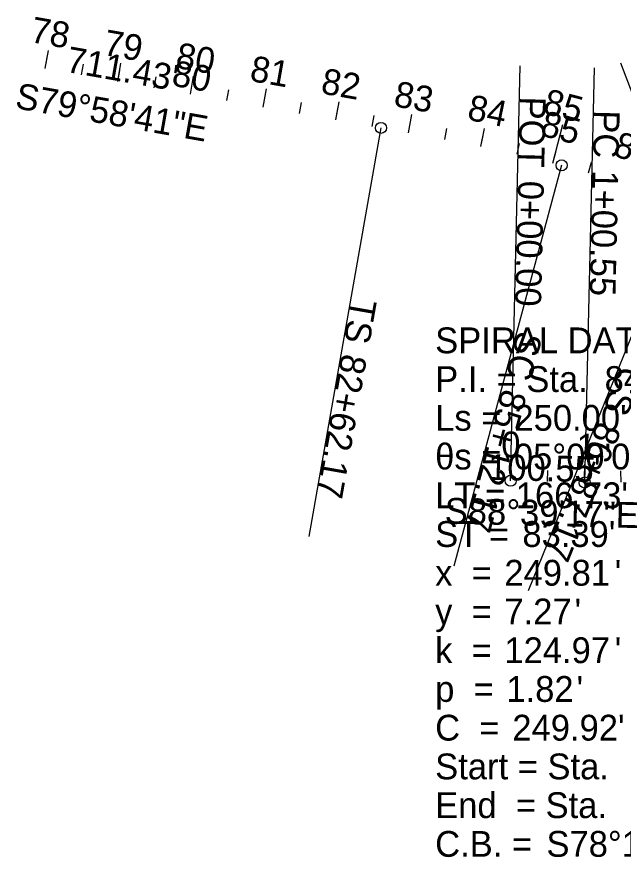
# Model space of a CAD drawing. Extents: x 2000474 to 2003418, y 251807 to 253801.
# Drawn here: x 2000474 to 2001296, y 252341 to 253480 of the extents above; entities that cross this region are included whole.
import ezdxf

# ---------------------------------------------------------------- set-up
doc = ezdxf.new("R2010")
doc.units = 0
for name, color, linetype in [('BD_X_Building', 7, 'Continuous'), ('DR_X_Flow_Arrow', 7, 'Continuous'), ('DV_X_Lot_Line', 7, 'Continuous'), ('DV_X_Property_Line', 7, 'Continuous'), ('DV_X_Township_Line', 7, 'Continuous'), ('GE_P_Alignment_100_Stations', 7, 'Continuous'), ('RW_P_Text', 7, 'Continuous'), ('RW_X_CL_100_Stations', 7, 'Continuous'), ('RW_X_CL_500_Stations', 7, 'Continuous'), ('SC_Scratch3', 7, 'Continuous'), ('SC_Scratch5', 7, 'Continuous'), ('SC_Shading1', 7, 'Continuous'), ('TX_X_50', 7, 'Continuous')]:
    doc.layers.add(name, color=color, linetype=linetype)

msp = doc.modelspace()

# ---------------------------------------------------------------- linework, layer by layer
at = {"layer": 'DR_X_Flow_Arrow'}
for p, q in [((2001143.5, 252851.1), (2001156.7, 253413.4)), ((2001490.7, 252890.5), (2001293.1, 253417.1)), ((2001244, 252848.7), (2001257.2, 253411)), ((2001143.5, 252851.1), (2001144.1, 252876.1)), ((2001243.5, 252848.7), (2001244.1, 252873.7)), ((2001193.5, 252849.9), (2001193.9, 252864.9)), ((2001293.5, 252849.4), (2001292.7, 252864.4))]:
    msp.add_line(p, q, dxfattribs=at)
for centre in [(2001143.5, 252851.1), (2001244, 252848.7)]:
    msp.add_circle(centre, 7.5, dxfattribs=at)
at = {"layer": 'DV_X_Lot_Line'}
for p, q in [((2001143.5, 252851.1), (2001144.1, 252876.1)), ((2001243.5, 252848.7), (2001243.8, 252863.7))]:
    msp.add_line(p, q, dxfattribs=at)
at = {"layer": 'DV_X_Property_Line'}
for p, q in [((2000512.7, 253409.8), (2000515.3, 253424.6)), ((2000611.2, 253392.4), (2000613.8, 253407.2)), ((2000709.7, 253375), (2000714, 253399.6)), ((2000808.1, 253357.6), (2000810.7, 253372.4)), ((2000906.6, 253340.2), (2000909.2, 253355)), ((2001005.1, 253322.8), (2001007.7, 253337.5)), ((2001200.8, 253281.8), (2001214.3, 253333.8)), ((2001103.3, 253304.2), (2001106.3, 253318.9))]:
    msp.add_line(p, q, dxfattribs=at)
at = {"layer": 'RW_P_Text'}
for p, q in [((2001143.5, 252851.1), (2001156.7, 253413.4)), ((2001490.7, 252890.5), (2001293.1, 253417.1)), ((2001244, 252848.7), (2001257.2, 253411)), ((2001143.5, 252851.1), (2001144.1, 252876.1))]:
    msp.add_line(p, q, dxfattribs=at)
for centre in [(2001143.5, 252851.1), (2001244, 252848.7)]:
    msp.add_circle(centre, 7.5, dxfattribs=at)
at = {"layer": 'RW_X_CL_100_Stations'}
for p, q in [((2001143.5, 252851.1), (2001156.7, 253413.4)), ((2001490.7, 252890.5), (2001293.1, 253417.1)), ((2001244, 252848.7), (2001257.2, 253411)), ((2000967.8, 253329.4), (2000869.9, 252775.4)), ((2001212.6, 253278.7), (2001066.8, 252735.5)), ((2001378.4, 253223.2), (2001167.5, 252701.7))]:
    msp.add_line(p, q, dxfattribs=at)
for centre in [(2000967.8, 253329.4), (2001212.6, 253278.7), (2001143.5, 252851.1), (2001244, 252848.7)]:
    msp.add_circle(centre, 7.5, dxfattribs=at)
at = {"layer": 'SC_Scratch3'}
for p, q in [((2000709.7, 253375), (2000714, 253399.6)), ((2000967.8, 253329.4), (2000869.9, 252775.4)), ((2001200.8, 253281.8), (2001204.6, 253296.4)), ((2001212.6, 253278.7), (2001066.8, 252735.5)), ((2001378.4, 253223.2), (2001167.5, 252701.7))]:
    msp.add_line(p, q, dxfattribs=at)
for centre in [(2000967.8, 253329.4), (2001212.6, 253278.7)]:
    msp.add_circle(centre, 7.5, dxfattribs=at)
at = {"layer": 'TX_X_50'}
for p, q in [((2000512.7, 253409.8), (2000517.1, 253434.4)), ((2000561.9, 253401.1), (2000564.6, 253415.9)), ((2000611.2, 253392.4), (2000615.5, 253417)), ((2000660.4, 253383.7), (2000663, 253398.5)), ((2000709.7, 253375), (2000714, 253399.6)), ((2000758.9, 253366.3), (2000761.5, 253381.1)), ((2000808.1, 253357.6), (2000812.5, 253382.2)), ((2000857.4, 253348.9), (2000860, 253363.7)), ((2000906.6, 253340.2), (2000911, 253364.8)), ((2000955.8, 253331.5), (2000958.5, 253346.3)), ((2001005.1, 253322.8), (2001009.5, 253347.4)), ((2000967.8, 253329.4), (2000869.9, 252775.4)), ((2001054.3, 253313.8), (2001057, 253328.5)), ((2001103.3, 253304.2), (2001108.3, 253328.7)), ((2001152.2, 253293.6), (2001155.5, 253308.3)), ((2001200.8, 253281.8), (2001207.1, 253306)), ((2001212.6, 253278.7), (2001066.8, 252735.5)), ((2001249, 253268.4), (2001253.2, 253282.8)), ((2001378.4, 253223.2), (2001167.5, 252701.7))]:
    msp.add_line(p, q, dxfattribs=at)
for centre in [(2000967.8, 253329.4), (2001212.6, 253278.7)]:
    msp.add_circle(centre, 7.5, dxfattribs=at)

# ---------------------------------------------------------------- texts
at = {"layer": 'BD_X_Building'}
for s, p in [("100.55'", (2001112.7, 252852.4)), ('S88°39\'17"E', (2001054, 252793.1))]:
    msp.add_text(s, height=35, rotation=358.6546, dxfattribs=at).set_placement(p)
at = {"layer": 'DR_X_Flow_Arrow'}
for s, rotation, p in [('POT', 268.6546, (2001156.3, 253372.2)), ('PC', 268.6546, (2001256.5, 253353.7)), ('1+00.55', 268.6546, (2001254.6, 253272.2)), ('0+00.00', 268.6546, (2001153.7, 253258.1)), ('0', 358.6546, (2001130.5, 252883.2)), ('1', 358.6546, (2001232.5, 252880.2))]:
    msp.add_text(s, height=35, rotation=rotation, dxfattribs=at).set_placement(p)
at = {"layer": 'DV_X_Lot_Line'}
msp.add_text('0', height=35, rotation=358.6546, dxfattribs=at).set_placement((2001130.5, 252883.2))
at = {"layer": 'DV_X_Property_Line'}
for s, rotation, p in [('80', 349.9781, (2000683, 253386.9)), ('85', 345.4529, (2001185.6, 253349.3))]:
    msp.add_text(s, height=35, rotation=rotation, dxfattribs=at).set_placement(p)
at = {"layer": 'DV_X_Township_Line'}
for s, p in [("100.55'", (2001112.7, 252852.4)), ('S88°39\'17"E', (2001054, 252793.1))]:
    msp.add_text(s, height=35, rotation=358.6546, dxfattribs=at).set_placement(p)
at = {"layer": 'GE_P_Alignment_100_Stations'}
for s, p in [("100.55'", (2001112.7, 252852.4)), ('S88°39\'17"E', (2001054, 252793.1))]:
    msp.add_text(s, height=35, rotation=358.6546, dxfattribs=at).set_placement(p)
at = {"layer": 'RW_P_Text'}
for s, rotation, p in [('POT', 268.6546, (2001156.3, 253372.2)), ('PC', 268.6546, (2001256.5, 253353.7)), ('1+00.55', 268.6546, (2001254.6, 253272.2)), ('0+00.00', 268.6546, (2001153.7, 253258.1)), ('0', 358.6546, (2001130.5, 252883.2))]:
    msp.add_text(s, height=35, rotation=rotation, dxfattribs=at).set_placement(p)
at = {"layer": 'RW_X_CL_100_Stations'}
for s, rotation, p in [("711.43'", 349.9781, (2000539.6, 253405.6)), ('S79°58\'41"E', 349.9781, (2000470.8, 253356.3)), ('POT', 268.6546, (2001156.3, 253372.2)), ('PC', 268.6546, (2001256.5, 253353.7)), ('1+00.55', 268.6546, (2001254.6, 253272.2)), ('0+00.00', 268.6546, (2001153.7, 253258.1)), ('TS', 259.9781, (2000927.8, 253099.4)), ('SC', 254.9781, (2001153.3, 253055.8)), ('82+62.17', 259.9781, (2000914.6, 253024.5)), ('CS', 247.9781, (2001292.4, 253009.1)), ('85+12.17', 254.9781, (2001132.2, 252977.1)), ('86+87.17', 247.9781, (2001261.9, 252933.5))]:
    msp.add_text(s, height=35, rotation=rotation, dxfattribs=at).set_placement(p)
at = {"layer": 'RW_X_CL_500_Stations'}
for s, p in [('SPIRAL DATA', (2001041.3, 253023.9)), ('P.I. = Sta. ', (2001041.3, 252971.4)), ('84+28.90', (2001270.9, 252971.4)), ('Ls = ', (2001041.3, 252918.9)), ("250.00'", (2001148.7, 252918.9)), ('θs = ', (2001041.3, 252866.4)), ('05°00\'00"', (2001148, 252866.4)), ('LT = ', (2001041.3, 252813.9)), ("166.73'", (2001150.5, 252813.9)), ('ST = ', (2001041.3, 252761.4)), ("83.39'", (2001159.5, 252761.4)), ('249.81', (2001135.1, 252708.9)), ("'", (2001284.6, 252708.9)), ('x  = ', (2001041.3, 252708.9)), ('y  = ', (2001041.3, 252656.4)), ('7.27', (2001135.1, 252656.4)), ("'", (2001230.2, 252656.4)), ('k  = ', (2001041.3, 252603.9)), ('124.97', (2001135.1, 252603.9)), ("'", (2001284.6, 252603.9)), ('1.82', (2001137.8, 252551.4)), ("'", (2001232.9, 252551.4)), ('p  = ', (2001041.3, 252551.4)), ('C  = ', (2001041.3, 252498.9)), ("249.92'", (2001145.9, 252498.9)), ('Start = Sta. ', (2001041.3, 252446.4)), ('End  = Sta. ', (2001041.3, 252393.9)), ('C.B. = ', (2001041.3, 252341.4)), ('S78°18\'41"E', (2001192.1, 252341.4))]:
    msp.add_text(s, height=35, dxfattribs=at).set_placement(p)
at = {"layer": 'SC_Scratch3'}
for s, rotation, p in [("711.43'", 349.9781, (2000539.6, 253405.6)), ('80', 349.9781, (2000688.2, 253411.1)), ('S79°58\'41"E', 349.9781, (2000470.8, 253356.3)), ('TS', 259.9781, (2000927.8, 253099.4)), ('SC', 254.9781, (2001153.3, 253055.8)), ('82+62.17', 259.9781, (2000914.6, 253024.5)), ('CS', 247.9781, (2001292.4, 253009.1)), ('85+12.17', 254.9781, (2001132.2, 252977.1)), ('86+87.17', 247.9781, (2001261.9, 252933.5))]:
    msp.add_text(s, height=35, rotation=rotation, dxfattribs=at).set_placement(p)
at = {"layer": 'SC_Scratch5'}
for s, p in [('SPIRAL DATA', (2001041.3, 253023.9)), ('P.I. = Sta. ', (2001041.3, 252971.4)), ('84+28.90', (2001270.9, 252971.4)), ('Ls = ', (2001041.3, 252918.9)), ("250.00'", (2001148.7, 252918.9)), ('θs = ', (2001041.3, 252866.4)), ('05°00\'00"', (2001148, 252866.4)), ('LT = ', (2001041.3, 252813.9)), ("166.73'", (2001150.5, 252813.9)), ('ST = ', (2001041.3, 252761.4)), ("83.39'", (2001159.5, 252761.4)), ('249.81', (2001135.1, 252708.9)), ("'", (2001284.6, 252708.9)), ('x  = ', (2001041.3, 252708.9)), ('y  = ', (2001041.3, 252656.4)), ('7.27', (2001135.1, 252656.4)), ("'", (2001230.2, 252656.4)), ('k  = ', (2001041.3, 252603.9)), ('124.97', (2001135.1, 252603.9)), ("'", (2001284.6, 252603.9)), ('1.82', (2001137.8, 252551.4)), ("'", (2001232.9, 252551.4)), ('p  = ', (2001041.3, 252551.4)), ('C  = ', (2001041.3, 252498.9)), ("249.92'", (2001145.9, 252498.9)), ('Start = Sta. ', (2001041.3, 252446.4)), ('End  = Sta. ', (2001041.3, 252393.9)), ('C.B. = ', (2001041.3, 252341.4)), ('S78°18\'41"E', (2001192.1, 252341.4))]:
    msp.add_text(s, height=35, dxfattribs=at).set_placement(p)
at = {"layer": 'SC_Shading1'}
for s, p in [('SPIRAL DATA', (2001041.3, 253023.9)), ('P.I. = Sta. ', (2001041.3, 252971.4)), ('84+28.90', (2001270.9, 252971.4)), ('Ls = ', (2001041.3, 252918.9)), ("250.00'", (2001148.7, 252918.9)), ('θs = ', (2001041.3, 252866.4)), ('05°00\'00"', (2001148, 252866.4)), ('LT = ', (2001041.3, 252813.9)), ("166.73'", (2001150.5, 252813.9)), ('ST = ', (2001041.3, 252761.4)), ("83.39'", (2001159.5, 252761.4)), ('249.81', (2001135.1, 252708.9)), ("'", (2001284.6, 252708.9)), ('x  = ', (2001041.3, 252708.9)), ('y  = ', (2001041.3, 252656.4)), ('7.27', (2001135.1, 252656.4)), ("'", (2001230.2, 252656.4)), ('k  = ', (2001041.3, 252603.9)), ('124.97', (2001135.1, 252603.9)), ("'", (2001284.6, 252603.9)), ('1.82', (2001137.8, 252551.4)), ("'", (2001232.9, 252551.4)), ('p  = ', (2001041.3, 252551.4)), ('C  = ', (2001041.3, 252498.9)), ("249.92'", (2001145.9, 252498.9)), ('Start = Sta. ', (2001041.3, 252446.4)), ('End  = Sta. ', (2001041.3, 252393.9)), ('C.B. = ', (2001041.3, 252341.4)), ('S78°18\'41"E', (2001192.1, 252341.4))]:
    msp.add_text(s, height=35, dxfattribs=at).set_placement(p)
at = {"layer": 'TX_X_50'}
for s, rotation, p in [('78', 349.9781, (2000491.3, 253445.9)), ('79', 349.9781, (2000590.1, 253428.5)), ("711.43'", 349.9781, (2000539.6, 253405.6)), ('80', 349.9781, (2000688.2, 253411.1)), ('81', 349.9781, (2000788.8, 253393.3)), ('82', 349.9781, (2000885.2, 253376.3)), ('S79°58\'41"E', 349.9781, (2000470.8, 253356.3)), ('83', 349.8636, (2000983.9, 253358.9)), ('84', 348.4583, (2001083.4, 253340.8)), ('85', 345.4529, (2001182.1, 253319.6)), ('86', 341.4648, (2001280.7, 253292.3)), ('TS', 259.9781, (2000927.8, 253099.4)), ('SC', 254.9781, (2001153.3, 253055.8)), ('82+62.17', 259.9781, (2000914.6, 253024.5)), ('CS', 247.9781, (2001292.4, 253009.1)), ('85+12.17', 254.9781, (2001132.2, 252977.1)), ('86+87.17', 247.9781, (2001261.9, 252933.5))]:
    msp.add_text(s, height=35, rotation=rotation, dxfattribs=at).set_placement(p)

doc.saveas('drawing.dxf')
